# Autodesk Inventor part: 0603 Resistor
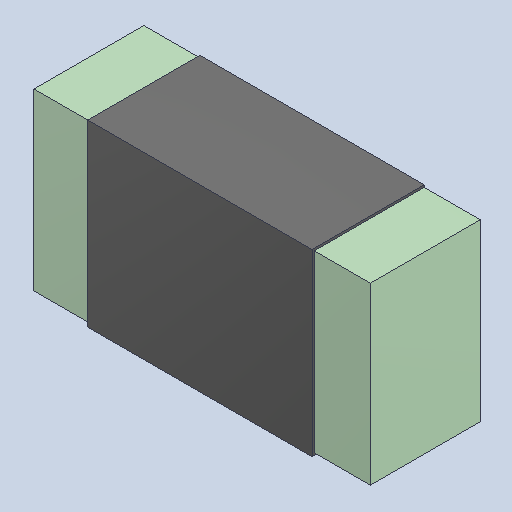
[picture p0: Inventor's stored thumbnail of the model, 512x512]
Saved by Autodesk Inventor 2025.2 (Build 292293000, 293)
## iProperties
Created: 2025-04
Part Number: 0603 Resistor
Material: Generic
Description: PART--DESC
Document SubType Name: Modeling
Designer: BennF
Density: 1 g/cm^3
Appearance: Default
Author: BennF
Revision Number: NONE
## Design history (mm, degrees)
feature "Solid1"
body "Solid2"
